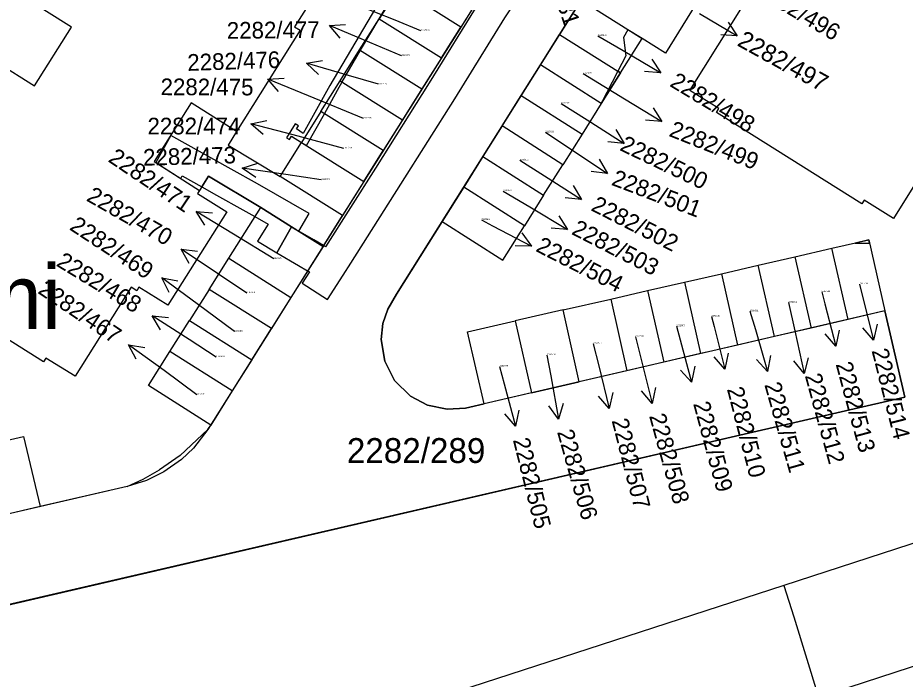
# Model space of a CAD drawing. Extents: x -785744 to -782822, y -1067550 to -1063910.
# Drawn here: x -783918.7 to -783857.9, y -1066065.2 to -1066019.9 of the extents above; entities that cross this region are included whole.
import ezdxf

# ---------------------------------------------------------------- set-up
doc = ezdxf.new("R2010")
doc.units = 0
for name, color, linetype in [('Hranice parcel', 7, 'Continuous'), ('Parcelní čísla', 7, 'Continuous'), ('Pop_ČP_popisy', 7, 'Continuous'), ('Vnitřní kresba', 7, 'Continuous'), ('Věcná břemena k části', 7, 'Continuous')]:
    doc.layers.add(name, color=color, linetype=linetype)

msp = doc.modelspace()

# ---------------------------------------------------------------- linework, layer by layer
at = {"layer": 'Hranice parcel'}
for p, q in [((-783895.92, -1066014.42), (-783899.75, -1066020.51)), ((-783892.65, -1066017.85), (-783893.97, -1066019.96)), ((-783888.37, -1066020.53), (-783892.65, -1066017.85)), ((-783915.03, -1066020.54), (-783918.39, -1066018.42)), ((-783887.04, -1066018.41), (-783888.37, -1066020.53)), ((-783880.14, -1066018.7), (-783881.61, -1066021.04)), ((-783880.14, -1066018.7), (-783875.96, -1066021.32)), ((-783895.3, -1066022.08), (-783893.97, -1066019.96)), ((-783893.97, -1066019.96), (-783889.7, -1066022.64)), ((-783917.55, -1066024.56), (-783915.03, -1066020.54)), ((-783899.37, -1066020.75), (-783903.72, -1066027.68)), ((-783899.75, -1066020.51), (-783899.37, -1066020.75)), ((-783889.7, -1066022.64), (-783888.37, -1066020.53)), ((-783882.92, -1066023.12), (-783881.61, -1066021.04)), ((-783881.61, -1066021.04), (-783877.44, -1066023.67)), ((-783877.44, -1066023.67), (-783875.96, -1066021.32)), ((-783874.36, -1066022.32), (-783875.96, -1066021.32)), ((-783896.63, -1066024.2), (-783895.3, -1066022.08)), ((-783895.3, -1066022.08), (-783891.03, -1066024.76)), ((-783920.92, -1066022.44), (-783917.55, -1066024.56)), ((-783889.7, -1066022.64), (-783891.03, -1066024.76)), ((-783884.23, -1066025.21), (-783882.92, -1066023.12)), ((-783878.76, -1066025.77), (-783882.92, -1066023.12)), ((-783877.44, -1066023.67), (-783878.76, -1066025.77)), ((-783897.95, -1066026.31), (-783896.63, -1066024.2)), ((-783896.63, -1066024.2), (-783892.36, -1066026.88)), ((-783891.03, -1066024.76), (-783892.36, -1066026.88)), ((-783885.54, -1066027.3), (-783884.23, -1066025.21)), ((-783884.23, -1066025.21), (-783880.07, -1066027.86)), ((-783878.76, -1066025.77), (-783880.07, -1066027.86)), ((-783897.95, -1066026.31), (-783899.28, -1066028.43)), ((-783893.68, -1066028.98), (-783897.95, -1066026.31)), ((-783892.36, -1066026.88), (-783893.68, -1066028.98)), ((-783903.72, -1066027.68), (-783904.3, -1066028.61)), ((-783885.54, -1066027.3), (-783886.86, -1066029.39)), ((-783881.38, -1066029.95), (-783885.54, -1066027.3)), ((-783880.07, -1066027.86), (-783881.38, -1066029.95)), ((-783904.3, -1066028.61), (-783900.74, -1066030.75)), ((-783900.74, -1066030.75), (-783899.28, -1066028.43)), ((-783899.28, -1066028.43), (-783895.02, -1066031.1)), ((-783895.02, -1066031.1), (-783893.68, -1066028.98)), ((-783886.86, -1066029.39), (-783888.17, -1066031.48)), ((-783886.86, -1066029.39), (-783882.7, -1066032.04)), ((-783882.7, -1066032.04), (-783881.38, -1066029.95)), ((-783905.65, -1066030.73), (-783906.27, -1066031.71)), ((-783902.07, -1066032.87), (-783905.65, -1066030.73)), ((-783895.02, -1066031.1), (-783896.48, -1066033.43)), ((-783906.27, -1066031.71), (-783906.4, -1066031.92)), ((-783906.4, -1066031.92), (-783904.4, -1066033.18)), ((-783888.17, -1066031.48), (-783889.64, -1066033.83)), ((-783884.01, -1066034.13), (-783888.17, -1066031.48)), ((-783882.7, -1066032.04), (-783884.01, -1066034.13)), ((-783904.4, -1066033.18), (-783908.42, -1066039.57)), ((-783904.26, -1066036.34), (-783902.07, -1066032.87)), ((-783889.64, -1066033.83), (-783892.78, -1066038.82)), ((-783889.64, -1066033.83), (-783885.49, -1066036.49)), ((-783885.49, -1066036.49), (-783884.01, -1066034.13)), ((-783897.8, -1066035.54), (-783900, -1066039.03)), ((-783862.96, -1066035.67), (-783860.43, -1066035.09)), ((-783860.43, -1066035.09), (-783859.33, -1066039.96)), ((-783868.01, -1066036.83), (-783865.49, -1066036.25)), ((-783865.49, -1066036.25), (-783862.96, -1066035.67)), ((-783865.49, -1066036.25), (-783864.38, -1066041.13)), ((-783861.85, -1066040.54), (-783862.96, -1066035.67)), ((-783905.6, -1066038.48), (-783904.26, -1066036.34)), ((-783904.26, -1066036.34), (-783900, -1066039.03)), ((-783870.53, -1066037.41), (-783868.01, -1066036.83)), ((-783866.9, -1066041.71), (-783868.01, -1066036.83)), ((-783916.93, -1066043.44), (-783926.88, -1066037.18)), ((-783873.05, -1066037.98), (-783870.53, -1066037.41)), ((-783870.53, -1066037.41), (-783869.42, -1066042.3)), ((-783875.58, -1066038.56), (-783873.05, -1066037.98)), ((-783873.05, -1066037.98), (-783871.95, -1066042.88)), ((-783910.95, -1066038.33), (-783914.78, -1066044.43)), ((-783910.56, -1066038.57), (-783910.95, -1066038.33)), ((-783910.41, -1066038.32), (-783910.56, -1066038.57)), ((-783908.42, -1066039.57), (-783910.41, -1066038.32)), ((-783905.6, -1066038.48), (-783906.95, -1066040.61)), ((-783901.34, -1066041.17), (-783905.6, -1066038.48)), ((-783878.1, -1066039.14), (-783875.58, -1066038.56)), ((-783875.58, -1066038.56), (-783874.47, -1066043.47)), ((-783900, -1066039.03), (-783901.34, -1066041.17)), ((-783892.78, -1066038.82), (-783893.37, -1066039.84)), ((-783881.37, -1066039.89), (-783878.1, -1066039.14)), ((-783878.1, -1066039.14), (-783877, -1066044.05)), ((-783893.37, -1066039.84), (-783893.7, -1066040.81)), ((-783881.37, -1066039.89), (-783884.64, -1066040.64)), ((-783880.26, -1066044.81), (-783881.37, -1066039.89)), ((-783859.33, -1066039.96), (-783861.85, -1066040.54)), ((-783859.33, -1066039.96), (-783857.96, -1066045.85)), ((-783908.29, -1066042.74), (-783906.95, -1066040.61)), ((-783906.95, -1066040.61), (-783902.68, -1066043.3)), ((-783893.7, -1066040.81), (-783893.82, -1066041.9)), ((-783887.91, -1066041.39), (-783884.64, -1066040.64)), ((-783884.64, -1066040.64), (-783883.52, -1066045.56)), ((-783861.85, -1066040.54), (-783864.38, -1066041.13)), ((-783902.68, -1066043.3), (-783901.34, -1066041.17)), ((-783886.78, -1066046.32), (-783887.91, -1066041.39)), ((-783866.9, -1066041.71), (-783869.42, -1066042.3)), ((-783864.38, -1066041.13), (-783866.9, -1066041.71)), ((-783893.82, -1066041.9), (-783893.57, -1066043.39)), ((-783869.42, -1066042.3), (-783871.42, -1066042.76)), ((-783909.76, -1066045.07), (-783908.29, -1066042.74)), ((-783904.02, -1066045.43), (-783908.29, -1066042.74)), ((-783871.95, -1066042.88), (-783874.47, -1066043.47)), ((-783871.42, -1066042.76), (-783871.95, -1066042.88)), ((-783916.77, -1066043.18), (-783916.93, -1066043.44)), ((-783914.78, -1066044.43), (-783916.77, -1066043.18)), ((-783902.68, -1066043.3), (-783904.02, -1066045.43)), ((-783893.57, -1066043.39), (-783892.9, -1066044.71)), ((-783874.47, -1066043.47), (-783877, -1066044.05)), ((-783877, -1066044.05), (-783880.26, -1066044.81)), ((-783892.9, -1066044.71), (-783891.82, -1066045.78)), ((-783905.49, -1066047.77), (-783909.76, -1066045.07)), ((-783883.52, -1066045.56), (-783880.26, -1066044.81)), ((-783904.02, -1066045.43), (-783905.49, -1066047.77)), ((-783891.82, -1066045.78), (-783890.64, -1066046.41)), ((-783883.52, -1066045.56), (-783886.78, -1066046.32)), ((-783857.96, -1066045.85), (-783869.56, -1066048.53)), ((-783890.64, -1066046.41), (-783889.3, -1066046.69)), ((-783888.05, -1066046.61), (-783886.78, -1066046.32)), ((-783889.3, -1066046.69), (-783888.05, -1066046.61)), ((-783905.69, -1066048.08), (-783905.49, -1066047.77)), ((-783905.69, -1066048.08), (-783906.44, -1066048.77)), ((-783869.56, -1066048.53), (-783940.09, -1066064.87)), ((-783921.8, -1066049.33), (-783918.32, -1066048.55)), ((-783918.32, -1066048.55), (-783917.16, -1066053.34)), ((-783906.44, -1066048.77), (-783907.58, -1066049.84)), ((-783907.58, -1066049.84), (-783908.99, -1066050.84)), ((-783910.12, -1066051.47), (-783908.99, -1066050.84)), ((-783911.22, -1066051.97), (-783917.16, -1066053.34)), ((-783911.22, -1066051.97), (-783910.12, -1066051.47)), ((-783917.16, -1066053.34), (-783920.64, -1066054.15)), ((-783863.88, -1066066.38), (-783834.72, -1066056.91)), ((-783866.26, -1066058.74), (-783905.99, -1066071.63)), ((-783866.26, -1066058.74), (-783865.56, -1066060.89)), ((-783865.56, -1066060.89), (-783863.88, -1066066.38))]:
    msp.add_line(p, q, dxfattribs=at)
for points in [[(-783871.08, -1066017.03), (-783874.36, -1066022.32)], [(-783872.69, -1066024.87), (-783868.86, -1066018.77)], [(-783870.7, -1066026.11), (-783872.69, -1066024.87)], [(-783870.86, -1066026.37), (-783870.7, -1066026.11)], [(-783860.91, -1066032.62), (-783870.86, -1066026.37)], [(-783854.95, -1066027.56), (-783858.75, -1066033.62)], [(-783896.48, -1066033.43), (-783900.74, -1066030.75)], [(-783860.76, -1066032.38), (-783860.91, -1066032.62)], [(-783858.75, -1066033.62), (-783860.76, -1066032.38)], [(-783902.07, -1066032.87), (-783897.8, -1066035.54)], [(-783897.8, -1066035.54), (-783896.48, -1066033.43)], [(-783837.42, -1066049.37), (-783866.26, -1066058.74)]]:
    msp.add_lwpolyline(points, dxfattribs=at)
at = {"layer": 'Pop_ČP_popisy'}
for p, q in [((-783892.87, -1066020.07), (-783895.658, -1066018.963)), ((-783872.03, -1066019.6), (-783869.452, -1066021.135)), ((-783894.6, -1066021.59), (-783897.368, -1066020.433)), ((-783877.26, -1066022.14), (-783874.67, -1066023.654)), ((-783896.06, -1066023.85), (-783898.94, -1066023.009)), ((-783898.8, -1066025.24), (-783901.577, -1066024.106)), ((-783877.17, -1066025.44), (-783874.609, -1066027.003)), ((-783879.71, -1066026.89), (-783877.181, -1066028.504)), ((-783899.84, -1066027.91), (-783902.741, -1066027.145)), ((-783880.83, -1066028.89), (-783878.33, -1066030.549)), ((-783900.36, -1066030.63), (-783903.329, -1066030.197)), ((-783882.64, -1066030.72), (-783880.116, -1066032.342)), ((-783903.93, -1066034.71), (-783906.494, -1066033.152)), ((-783883.64, -1066032.84), (-783881.071, -1066034.389)), ((-783886.19, -1066034.13), (-783883.537, -1066035.53)), ((-783905.02, -1066037.4), (-783907.517, -1066035.737)), ((-783906.42, -1066039.48), (-783908.836, -1066037.701)), ((-783860.84, -1066039.05), (-783860.112, -1066041.96)), ((-783863.45, -1066039.47), (-783862.7, -1066042.375)), ((-783906.97, -1066041.91), (-783909.491, -1066040.283)), ((-783871.03, -1066041.03), (-783870.302, -1066043.94)), ((-783868.2, -1066041.23), (-783867.365, -1066044.111)), ((-783865.5, -1066041.31), (-783864.855, -1066044.24)), ((-783908.69, -1066044.04), (-783911.112, -1066042.27)), ((-783873.35, -1066041.94), (-783872.58, -1066044.839)), ((-783876, -1066043.37), (-783875.272, -1066046.28)), ((-783878.92, -1066043.72), (-783878.211, -1066046.635)), ((-783882.21, -1066044.4), (-783881.684, -1066047.354)), ((-783885.39, -1066044.94), (-783884.622, -1066047.84))]:
    msp.add_line(p, q, dxfattribs=at)
for points in [[(-783896.638, -1066021.28), (-783897.368, -1066020.433), (-783896.253, -1066020.358)], [(-783891.1, -1066020.78), (-783892.87, -1066020.07)], [(-783870.056, -1066020.194), (-783869.452, -1066021.135), (-783870.567, -1066021.053)], [(-783892.44, -1066022.5), (-783894.6, -1066021.59)], [(-783878.98, -1066021.14), (-783877.26, -1066022.14)], [(-783898.12, -1066023.769), (-783898.94, -1066023.009), (-783897.84, -1066022.809)], [(-783875.281, -1066022.718), (-783874.67, -1066023.654), (-783875.786, -1066023.581)], [(-783900.841, -1066024.947), (-783901.577, -1066024.106), (-783900.463, -1066024.021)], [(-783894.01, -1066024.45), (-783896.06, -1066023.85)], [(-783880, -1066023.72), (-783877.17, -1066025.44)], [(-783895.04, -1066026.78), (-783898.8, -1066025.24)], [(-783881.5, -1066025.76), (-783879.71, -1066026.89)], [(-783875.202, -1066026.055), (-783874.609, -1066027.003), (-783875.723, -1066026.909)], [(-783901.901, -1066027.883), (-783902.741, -1066027.145), (-783901.646, -1066026.917)], [(-783882.58, -1066027.73), (-783880.83, -1066028.89)], [(-783877.755, -1066027.544), (-783877.181, -1066028.504), (-783878.293, -1066028.387)], [(-783896.38, -1066028.83), (-783899.84, -1066027.91)], [(-783902.411, -1066030.836), (-783903.329, -1066030.197), (-783902.267, -1066029.846)], [(-783884.32, -1066029.65), (-783882.64, -1066030.72)], [(-783878.887, -1066029.579), (-783878.33, -1066030.549), (-783879.44, -1066030.412)], [(-783897.92, -1066030.99), (-783900.36, -1066030.63)], [(-783880.687, -1066031.381), (-783880.116, -1066032.342), (-783881.228, -1066032.222)], [(-783885.46, -1066031.75), (-783883.64, -1066032.84)], [(-783905.899, -1066034.098), (-783906.494, -1066033.152), (-783905.379, -1066033.244)], [(-783886.95, -1066033.73), (-783886.19, -1066034.13)], [(-783881.669, -1066033.444), (-783881.071, -1066034.389), (-783882.185, -1066034.301)], [(-783901.17, -1066036.4), (-783903.93, -1066034.71)], [(-783884.188, -1066034.621), (-783883.537, -1066035.53), (-783884.655, -1066035.506)], [(-783906.962, -1066036.708), (-783907.517, -1066035.737), (-783906.408, -1066035.875)], [(-783903.03, -1066038.73), (-783905.02, -1066037.4)], [(-783908.327, -1066038.697), (-783908.836, -1066037.701), (-783907.734, -1066037.891)], [(-783863.66, -1066038.66), (-783863.45, -1066039.47)], [(-783861.08, -1066038.12), (-783860.84, -1066039.05)], [(-783903.87, -1066041.37), (-783906.42, -1066039.48)], [(-783865.93, -1066039.38), (-783865.5, -1066041.31)], [(-783908.922, -1066041.246), (-783909.491, -1066040.283), (-783908.379, -1066040.405)], [(-783871.21, -1066040.34), (-783871.03, -1066041.03)], [(-783868.57, -1066039.98), (-783868.2, -1066041.23)], [(-783873.6, -1066041), (-783873.35, -1066041.94)], [(-783859.87, -1066040.869), (-783860.112, -1066041.96), (-783860.84, -1066041.112)], [(-783876.42, -1066041.72), (-783876, -1066043.37)], [(-783862.466, -1066041.282), (-783862.7, -1066042.375), (-783863.434, -1066041.531)], [(-783910.6, -1066043.264), (-783911.112, -1066042.27), (-783910.01, -1066042.456)], [(-783905.13, -1066043.11), (-783906.97, -1066041.91)], [(-783879.3, -1066042.2), (-783878.92, -1066043.72)], [(-783870.06, -1066042.849), (-783870.302, -1066043.94), (-783871.03, -1066043.092)], [(-783882.47, -1066042.98), (-783882.21, -1066044.4)], [(-783867.163, -1066043.012), (-783867.365, -1066044.111), (-783868.123, -1066043.29)], [(-783864.582, -1066043.156), (-783864.855, -1066044.24), (-783865.558, -1066043.371)], [(-783906.44, -1066045.69), (-783908.69, -1066044.04)], [(-783885.71, -1066043.76), (-783885.39, -1066044.94)], [(-783872.353, -1066043.745), (-783872.58, -1066044.839), (-783873.32, -1066044.001)], [(-783875.03, -1066045.189), (-783875.272, -1066046.28), (-783876, -1066045.432)], [(-783877.961, -1066045.545), (-783878.211, -1066046.635), (-783878.933, -1066045.782)], [(-783881.367, -1066046.281), (-783881.684, -1066047.354), (-783882.352, -1066046.457)], [(-783884.395, -1066046.745), (-783884.622, -1066047.84), (-783885.362, -1066047.001)]]:
    msp.add_lwpolyline(points, dxfattribs=at)
at = {"layer": 'Vnitřní kresba'}
for p, q in [((-783906.84, -1066025.71), (-783909.37, -1066029.74)), ((-783903.72, -1066027.68), (-783906.84, -1066025.71)), ((-783909.37, -1066029.74), (-783906.27, -1066031.71))]:
    msp.add_line(p, q, dxfattribs=at)
at = {"layer": 'Věcná břemena k části'}
for p, q in [((-783881.92, -1066010.26), (-783897.56, -1066035.15)), ((-783885.35, -1066019.91), (-783883.59, -1066017.24)), ((-783892.78, -1066038.82), (-783879.52, -1066017.71)), ((-783887.09, -1066018.79), (-783890.54, -1066024.35)), ((-783888.78, -1066025.45), (-783885.35, -1066019.91)), ((-783890.54, -1066024.35), (-783894.21, -1066030.19)), ((-783892.47, -1066031.29), (-783888.78, -1066025.45)), ((-783894.21, -1066030.19), (-783897.63, -1066035.57)), ((-783895.89, -1066036.69), (-783892.47, -1066031.29)), ((-783899.95, -1066034.21), (-783900.97, -1066035.98)), ((-783897.56, -1066035.15), (-783904.91, -1066046.84)), ((-783900.97, -1066035.98), (-783899.48, -1066036.84)), ((-783896.43, -1066037.52), (-783895.89, -1066036.69)), ((-783898.74, -1066037.29), (-783899.23, -1066038.05)), ((-783899.23, -1066038.05), (-783897.49, -1066039.17)), ((-783897.49, -1066039.17), (-783896.43, -1066037.52)), ((-783893.37, -1066039.84), (-783892.78, -1066038.82)), ((-783893.7, -1066040.81), (-783893.37, -1066039.84)), ((-783893.82, -1066041.9), (-783893.7, -1066040.81)), ((-783893.57, -1066043.39), (-783893.82, -1066041.9)), ((-783871.42, -1066042.76), (-783888.05, -1066046.61)), ((-783892.9, -1066044.71), (-783893.57, -1066043.39)), ((-783891.82, -1066045.78), (-783892.9, -1066044.71)), ((-783890.64, -1066046.41), (-783891.82, -1066045.78)), ((-783889.3, -1066046.69), (-783890.64, -1066046.41)), ((-783904.91, -1066046.84), (-783905.69, -1066048.08)), ((-783888.05, -1066046.61), (-783889.3, -1066046.69)), ((-783905.69, -1066048.08), (-783906.67, -1066049.34)), ((-783937.06, -1066064.17), (-783869.56, -1066048.53)), ((-783906.67, -1066049.34), (-783907.5, -1066050.12)), ((-783907.5, -1066050.12), (-783908.71, -1066050.97)), ((-783908.71, -1066050.97), (-783909.89, -1066051.55)), ((-783911.22, -1066051.97), (-783938.43, -1066058.26)), ((-783909.89, -1066051.55), (-783911.22, -1066051.97))]:
    msp.add_line(p, q, dxfattribs=at)
for points in [[(-783881.92, -1066010.26), (-783897.56, -1066035.15)], [(-783893.32, -1066017.7), (-783897.33, -1066024.54), (-783899.16, -1066027.82), (-783899.62, -1066027.5), (-783899.49, -1066027.29), (-783899.7, -1066027.16), (-783900.3, -1066028.1), (-783900.09, -1066028.23), (-783899.95, -1066028), (-783899.28, -1066028.43), (-783898.94, -1066028.64), (-783897.71, -1066026.46), (-783896.81, -1066024.84), (-783896.49, -1066024.29), (-783895.23, -1066022.12), (-783893.97, -1066019.96), (-783892.8, -1066018)], [(-783893.7, -1066040.81), (-783893.37, -1066039.84), (-783892.78, -1066038.82), (-783879.52, -1066017.71)], [(-783876.93, -1066020.71), (-783877.24, -1066021.25)], [(-783875.96, -1066021.32), (-783876.93, -1066020.71)], [(-783877.44, -1066023.67), (-783875.96, -1066021.32)], [(-783877.24, -1066021.25), (-783877.06, -1066022.49)], [(-783877.06, -1066022.49), (-783877.62, -1066023.56)], [(-783877.62, -1066023.56), (-783878.76, -1066025.77)], [(-783878.76, -1066025.77), (-783877.44, -1066023.67)], [(-783877.44, -1066023.67), (-783877.62, -1066023.56)], [(-783877.62, -1066023.56), (-783877.44, -1066023.67)], [(-783908.22, -1066027.96), (-783909.25, -1066029.81)], [(-783904.1, -1066030.25), (-783908.22, -1066027.96)], [(-783909.25, -1066029.81), (-783907.54, -1066030.9)], [(-783907.54, -1066030.9), (-783907.44, -1066030.72)], [(-783907.44, -1066030.72), (-783906.11, -1066031.46)], [(-783905.65, -1066030.73), (-783906.11, -1066031.46)], [(-783906.11, -1066031.46), (-783905.65, -1066030.73)], [(-783902.07, -1066032.87), (-783905.65, -1066030.73)], [(-783905.65, -1066030.73), (-783902.07, -1066032.87)], [(-783902.29, -1066031.27), (-783904.1, -1066030.25)], [(-783898.75, -1066033.3), (-783902.29, -1066031.27)], [(-783906.11, -1066031.46), (-783905.09, -1066032.03)], [(-783905.09, -1066032.03), (-783903.29, -1066033.03)], [(-783903.29, -1066033.03), (-783902.47, -1066033.5)], [(-783899.95, -1066034.21), (-783902.07, -1066032.87)], [(-783902.07, -1066032.87), (-783899.95, -1066034.21)], [(-783902.47, -1066033.5), (-783901.57, -1066034.02)], [(-783899.47, -1066034.49), (-783898.75, -1066033.3)], [(-783901.57, -1066034.02), (-783902.28, -1066035.19)], [(-783900.97, -1066035.98), (-783899.95, -1066034.21)], [(-783898.44, -1066035.08), (-783899.66, -1066034.38), (-783899.95, -1066034.21)], [(-783899.95, -1066034.21), (-783899.66, -1066034.38)], [(-783899.66, -1066034.38), (-783899.47, -1066034.49)], [(-783897.56, -1066035.15), (-783904.91, -1066046.84)], [(-783902.28, -1066035.19), (-783900.97, -1066035.98)], [(-783897.63, -1066035.57), (-783897.77, -1066035.49), (-783898.44, -1066035.08)], [(-783860.43, -1066035.09), (-783861.38, -1066035.31)], [(-783861.38, -1066035.31), (-783860.38, -1066035.32)], [(-783860.38, -1066035.32), (-783860.43, -1066035.09)], [(-783899.48, -1066036.84), (-783898.86, -1066037.22), (-783898.74, -1066037.29)], [(-783857.96, -1066045.85), (-783859.33, -1066039.96), (-783871.42, -1066042.76), (-783888.05, -1066046.61), (-783889.3, -1066046.69)], [(-783859.33, -1066039.96), (-783871.42, -1066042.76)], [(-783857.96, -1066045.85), (-783859.33, -1066039.96)], [(-783892.9, -1066044.71), (-783893.57, -1066043.39), (-783893.82, -1066041.9), (-783893.7, -1066040.81)], [(-783889.3, -1066046.69), (-783890.64, -1066046.41), (-783891.82, -1066045.78), (-783892.9, -1066044.71)], [(-783937.06, -1066064.17), (-783869.56, -1066048.53), (-783857.96, -1066045.85)], [(-783869.56, -1066048.53), (-783857.96, -1066045.85)], [(-783904.91, -1066046.84), (-783905.69, -1066048.08), (-783906.67, -1066049.34), (-783907.5, -1066050.12), (-783908.71, -1066050.97), (-783909.89, -1066051.55), (-783911.22, -1066051.97), (-783938.43, -1066058.26), (-783937.06, -1066064.17)]]:
    msp.add_lwpolyline(points, dxfattribs=at)

# ---------------------------------------------------------------- texts
at = {"layer": 'Parcelní čísla'}
for s, height, p in [('2282/478', 0.1, (-783891.1, -1066020.78)), ('2282/498', 0.1, (-783878.98, -1066021.14)), ('2282/477', 0.1, (-783892.44, -1066022.5)), ('2282/499', 0.1, (-783880, -1066023.72)), ('2282/476', 0.1, (-783894.01, -1066024.45)), ('2282/500', 0.1, (-783881.5, -1066025.76)), ('2282/475', 0.1, (-783895.04, -1066026.78)), ('2282/501', 0.1, (-783882.58, -1066027.73)), ('2282/474', 0.1, (-783896.38, -1066028.83)), ('2282/502', 0.1, (-783884.32, -1066029.65)), ('2282/473', 0.1, (-783897.92, -1066030.99)), ('2282/503', 0.1, (-783885.46, -1066031.75)), ('2282/504', 0.1, (-783886.95, -1066033.73)), ('2282/471', 0.1, (-783901.17, -1066036.4)), ('2282/514', 0.1, (-783861.08, -1066038.12)), ('2282/470', 0.1, (-783903.03, -1066038.73)), ('2282/513', 0.1, (-783863.66, -1066038.66)), ('2282/512', 0.1, (-783865.93, -1066039.38)), ('2282/511', 0.1, (-783868.57, -1066039.98)), ('2282/510', 0.1, (-783871.21, -1066040.34)), ('2282/509', 0.1, (-783873.6, -1066041)), ('2282/469', 0.1, (-783903.87, -1066041.37)), ('2282/508', 0.1, (-783876.42, -1066041.72)), ('2282/507', 0.1, (-783879.3, -1066042.2)), ('2282/506', 0.1, (-783882.47, -1066042.98)), ('2282/468', 0.1, (-783905.13, -1066043.11)), ('2282/505', 0.1, (-783885.71, -1066043.76)), ('2282/467', 0.1, (-783906.44, -1066045.69)), ('2282/289', 1.7, (-783896.17, -1066050.36))]:
    msp.add_text(s, height=height, dxfattribs=at).set_placement(p)
at = {"layer": 'Pop_ČP_popisy'}
for s, height, rotation, p in [('2282/431', 1.14, 288.45414, (-783883.268, -1066014.54)), ('2282/496', 1.14, 329.40684, (-783868.308, -1066018.269)), ('2282/477', 1.14, 0.60417, (-783904.384, -1066021.335)), ('2282/497', 1.2, 331.14267, (-783869.514, -1066021.764)), ('2282/476', 1.14, 1.92303, (-783907.076, -1066023.533)), ('2282/475', 1.14, 359.82459, (-783908.925, -1066025.19)), ('2282/498', 1.14, 328.99932, (-783874.126, -1066024.542)), ('2282/474', 1.14, 0.15651, (-783909.818, -1066027.879)), ('2282/499', 1.14, 338.25825, (-783874.18, -1066027.97)), ('2282/500', 1.14, 334.38897, (-783877.551, -1066028.934)), ('2282/471', 1.15, 326.16774, (-783912.578, -1066029.699)), ('2282/473', 1.14, 1.52892, (-783910.108, -1066030.021)), ('2282/501', 1.14, 339.14583, (-783878.117, -1066031.317)), ('2282/470', 1.14, 330.31134, (-783914.068, -1066032.379)), ('2282/502', 1.14, 333.01944, (-783879.519, -1066033.047)), ('2282/469', 1.14, 326.7297, (-783915.224, -1066034.354)), ('2282/503', 1.14, 332.8164, (-783880.85, -1066034.673)), ('2282/504', 1.14, 333.07362, (-783883.302, -1066035.84)), ('2282/468', 1.14, 328.69566, (-783916.126, -1066036.836)), ('2282/467', 1.14, 325.97874, (-783917.39, -1066038.7)), ('2282/514', 1.14, 284.16429, (-783860.249, -1066042.675)), ('2282/513', 1.14, 285.05457, (-783862.711, -1066043.598)), ('2282/512', 1.14, 285.28011, (-783864.821, -1066044.389)), ('2282/510', 1.14, 284.37894, (-783870.154, -1066045.302)), ('2282/511', 1.14, 285.87159, (-783867.595, -1066044.998)), ('2282/509', 1.14, 285.08688, (-783872.467, -1066046.304)), ('2282/508', 1.14, 285.51267, (-783875.485, -1066047.139)), ('2282/507', 1.14, 284.37624, (-783878.049, -1066047.456)), ('2282/506', 1.14, 285.75198, (-783881.785, -1066048.234)), ('2282/505', 1.14, 283.96584, (-783884.808, -1066048.78))]:
    msp.add_text(s, height=height, rotation=rotation, dxfattribs=at).set_placement(p)
msp.add_text('Za bytovkami', height=4.4, dxfattribs=at).set_placement((-783950.73, -1066041.19))

doc.saveas('drawing.dxf')
